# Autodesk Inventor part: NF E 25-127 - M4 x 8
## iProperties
Created: 2007-08
Part Number: NF E 25-127 - M4 x 8
Material: Stahl, weich, unlegiert
Description: Zylinderschraube mit Schlitz
Vendor: Autodesk Inc.
Document SubType Name: Modeling
Standard: NF E25-127
Designer: Ulrich
Standards Organization: AFNOR
Language: de-DE
Size Designation: M4 x 8
Categories: <MemberInstance Version="R10.0.0"><Categories><Category DisplayName="Schrauben" InternalName="e4da775c-781d-43d5-af7c-5136215cf5a6" Mnemonic="FSTN"><Category Di
Author: Ulrich
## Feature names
1. Körper [Revolution]
2. Rundung1 [Fillet]
3. Loch [Extrusion]
4. Fase1 [Chamfer]
